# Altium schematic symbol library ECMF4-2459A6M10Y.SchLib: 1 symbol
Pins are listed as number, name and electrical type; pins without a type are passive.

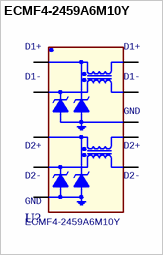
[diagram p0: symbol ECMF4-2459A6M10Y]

## ECMF4-2459A6M10Y
designator U?
footprint ST_QFN50P260X135X70-10L (Footprint not found)
pins: 1 D1+, 2 D1-, 3 GND, 4 D2+, 5 D2-, 6 D2-1, 7 D2+1, 8 GND1, 9 D1-1, 10 D1+1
